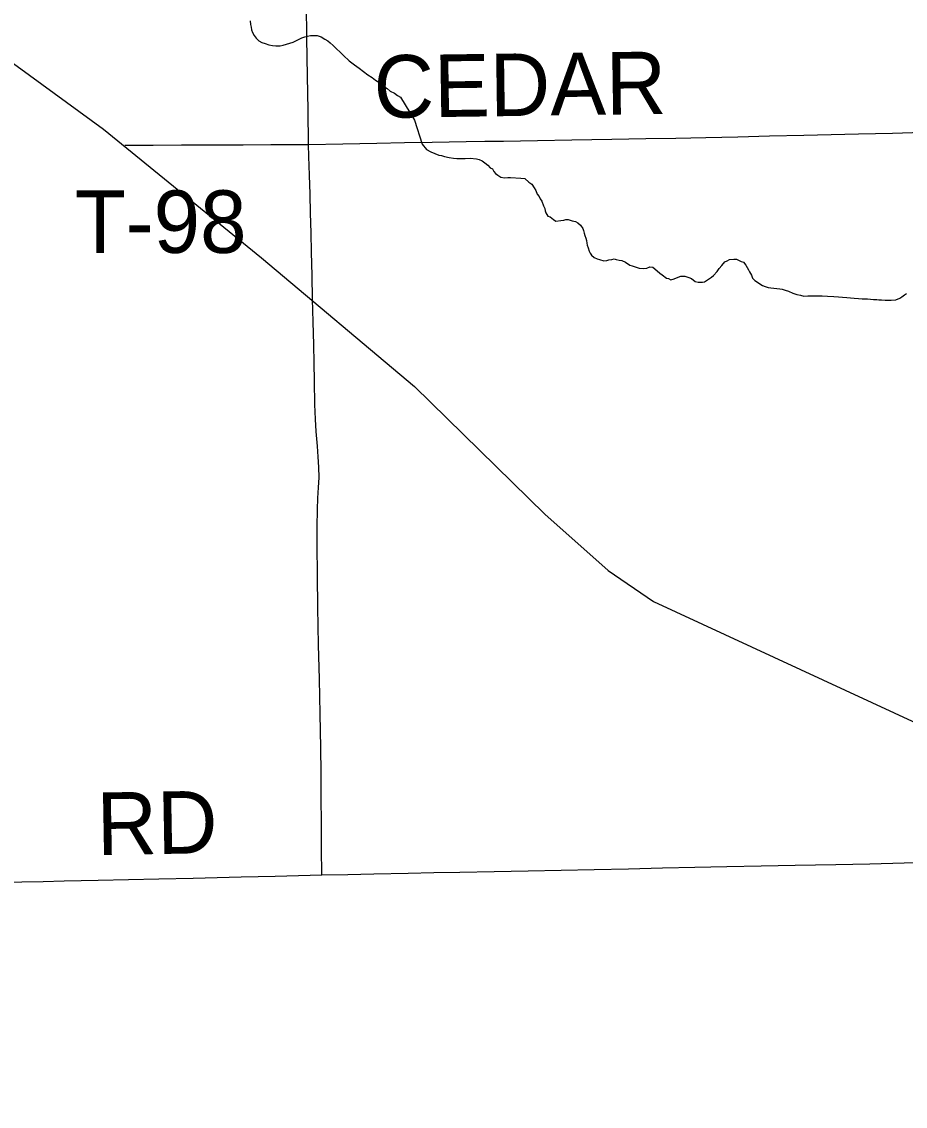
# Model space of a CAD drawing. Extents: x -11.4 to 84.1, y 11.1 to 59.
# Drawn here: x 31.559 to 32.362, y 45.761 to 46.747 of the extents above; entities that cross this region are included whole.
import ezdxf

# ---------------------------------------------------------------- set-up
doc = ezdxf.new("R2010")
doc.units = 0
for name, color, linetype in [('GM_X_County_Road', 7, 'Continuous'), ('GM_X_County_Road_Text', 7, 'Continuous'), ('GM_X_Minor_River', 7, 'Continuous'), ('GM_X_Rail_Line', 7, 'Continuous'), ('GM_X_Township_Road', 7, 'Continuous'), ('GM_X_Township_Road_Text', 7, 'Continuous')]:
    doc.layers.add(name, color=color, linetype=linetype)

msp = doc.modelspace()

# ---------------------------------------------------------------- linework, layer by layer
at = {"layer": 'GM_X_County_Road'}
msp.add_lwpolyline([(31.52787, 45.96386), (31.55893, 45.96467), (31.57804, 45.96516), (31.59715, 45.96566), (31.62821, 45.9663), (31.65581, 45.96686), (31.6834, 45.96744), (31.71446, 45.96819), (31.73633, 45.96872), (31.7582, 45.96924), (31.78925, 45.97002), (31.81035, 45.97055), (31.83145, 45.97107), (31.85514, 45.97151), (31.87883, 45.97196), (31.90989, 45.97264), (31.93349, 45.97316), (31.95709, 45.97367), (31.98815, 45.97428), (32.01921, 45.97489), (32.04922, 45.97548), (32.07924, 45.97607), (32.1103, 45.97674), (32.14137, 45.97742), (32.17056, 45.97805), (32.19975, 45.97869), (32.23081, 45.97932), (32.26187, 45.97994), (32.2803, 45.9803), (32.29872, 45.98067), (32.32978, 45.9813), (32.36085, 45.98193), (32.39191, 45.98256)], dxfattribs=at)
at = {"layer": 'GM_X_Minor_River'}
for points in [[(31.76638, 46.74748), (31.7668, 46.74406), (31.76721, 46.74178), (31.76762, 46.73912), (31.76841, 46.73685), (31.76996, 46.7342), (31.77189, 46.73156), (31.7742, 46.7293), (31.77687, 46.72781), (31.77993, 46.7267), (31.78336, 46.72559), (31.78679, 46.72487), (31.78984, 46.72452), (31.79364, 46.72456), (31.79629, 46.72534), (31.80538, 46.72809), (31.8084, 46.72964), (31.81105, 46.73081), (31.81332, 46.73197), (31.81597, 46.73276), (31.81862, 46.73355), (31.82128, 46.73395), (31.82432, 46.73399), (31.82736, 46.73401), (31.8308, 46.73291), (31.83424, 46.73066), (31.83692, 46.72917), (31.83922, 46.72729), (31.84191, 46.72504), (31.84499, 46.72202), (31.84806, 46.71901), (31.85114, 46.716), (31.85652, 46.71111), (31.86112, 46.70736), (31.86534, 46.70436), (31.86956, 46.70136), (31.87339, 46.69835), (31.87722, 46.69573), (31.88029, 46.69348), (31.88336, 46.69161), (31.88604, 46.68935), (31.88835, 46.68748), (31.89102, 46.68598), (31.89372, 46.68335), (31.89754, 46.68149), (31.90022, 46.67961), (31.9029, 46.67812), (31.91574, 46.65719)], [(31.91574, 46.65719), (31.92276, 46.63529), (31.92664, 46.63041), (31.93048, 46.62819), (31.9343, 46.62673), (31.93775, 46.62527), (31.94041, 46.62493), (31.94308, 46.62421), (31.94728, 46.62314), (31.95109, 46.62244), (31.95413, 46.62212), (31.96172, 46.62224), (31.96628, 46.62269), (31.97199, 46.62203), (31.97465, 46.62131), (31.97733, 46.62021), (31.97964, 46.61835), (31.98234, 46.61611), (31.98466, 46.61387), (31.98657, 46.61276), (31.98775, 46.6105), (31.9893, 46.60862), (31.99161, 46.60714), (31.9943, 46.60528), (31.99773, 46.60458), (32.00076, 46.60501), (32.00304, 46.60504), (32.01254, 46.60444), (32.01597, 46.60411), (32.01982, 46.60076), (32.02251, 46.5989), (32.02447, 46.59551), (32.02602, 46.59325), (32.02722, 46.58985), (32.02916, 46.5876), (32.02995, 46.58571), (32.0315, 46.58345), (32.03309, 46.5793), (32.03428, 46.57666), (32.03469, 46.57476), (32.0351, 46.57287), (32.03705, 46.56986), (32.03896, 46.56913), (32.04204, 46.5669), (32.04434, 46.56541), (32.04889, 46.56587), (32.05154, 46.56629), (32.05344, 46.5667), (32.05533, 46.56674), (32.05915, 46.56566), (32.0622, 46.56495), (32.06412, 46.56384), (32.06682, 46.5616), (32.06877, 46.55859), (32.06956, 46.5567), (32.06997, 46.55443), (32.07077, 46.55216), (32.07157, 46.54989), (32.07199, 46.54761), (32.07241, 46.54534), (32.07282, 46.54344), (32.07361, 46.54118), (32.07443, 46.53815), (32.0756, 46.53627), (32.07677, 46.53438), (32.07908, 46.53214), (32.08176, 46.53104), (32.08405, 46.53032), (32.08787, 46.52924), (32.09052, 46.52967), (32.09241, 46.53008), (32.09506, 46.5305), (32.09734, 46.53092), (32.09924, 46.53057), (32.10191, 46.52985), (32.1042, 46.52951), (32.10764, 46.52805), (32.11148, 46.52545), (32.11377, 46.52472), (32.11989, 46.52254), (32.12369, 46.52222), (32.1271, 46.52266), (32.12974, 46.52384), (32.1324, 46.52351), (32.13626, 46.52015), (32.13896, 46.51791), (32.14088, 46.51642), (32.14473, 46.51344), (32.14663, 46.51309), (32.14893, 46.51199), (32.15196, 46.5128), (32.15535, 46.51438), (32.15799, 46.51518), (32.16141, 46.51524), (32.16523, 46.51416), (32.16753, 46.51306), (32.17099, 46.51045), (32.17366, 46.50974)], [(32.17366, 46.50974), (32.17746, 46.5098), (32.17935, 46.51021), (32.18123, 46.51138), (32.18311, 46.51255), (32.18573, 46.51449), (32.18761, 46.51605), (32.19097, 46.51952), (32.19282, 46.52222), (32.19505, 46.52492), (32.19804, 46.52839), (32.19992, 46.52918), (32.20218, 46.53036), (32.20597, 46.5308), (32.20863, 46.53084), (32.21284, 46.52863), (32.21476, 46.5279), (32.21708, 46.52528), (32.21943, 46.52113), (32.22022, 46.51924), (32.22217, 46.51623), (32.22297, 46.51359), (32.22529, 46.51134), (32.2322, 46.50689), (32.2345, 46.50579), (32.23717, 46.50507), (32.23983, 46.50474), (32.2425, 46.5044), (32.24516, 46.50406), (32.24783, 46.50373), (32.25011, 46.50338), (32.25278, 46.50267), (32.25584, 46.50158), (32.25967, 46.49974), (32.26349, 46.49866), (32.26654, 46.49795), (32.26959, 46.49724), (32.27338, 46.4973), (32.2768, 46.49736), (32.28022, 46.49741), (32.28364, 46.49747), (32.28629, 46.49751), (32.29124, 46.49721), (32.29694, 46.49692), (32.30112, 46.49661), (32.30493, 46.4963), (32.30873, 46.49598), (32.31215, 46.49565), (32.31558, 46.49533), (32.31938, 46.49501), (32.32281, 46.49469), (32.32546, 46.49473), (32.32774, 46.49477), (32.33307, 46.4941), (32.33611, 46.49415), (32.33801, 46.4938), (32.34029, 46.49383), (32.34372, 46.49351), (32.34713, 46.49357), (32.34903, 46.4936), (32.35321, 46.49367), (32.35698, 46.49525), (32.35886, 46.49642), (32.36111, 46.49836), (32.36299, 46.49953)]]:
    msp.add_lwpolyline(points, dxfattribs=at)
at = {"layer": 'GM_X_Rail_Line'}
msp.add_lwpolyline([(31.09667, 47.00784), (31.1415, 46.99148), (31.18544, 46.9755), (31.63289, 46.64907), (31.77669, 46.5321), (31.91579, 46.41507), (32.03416, 46.29896), (32.09173, 46.24782), (32.13318, 46.21971), (32.55048, 46.02665), (32.76419, 45.92575), (32.90652, 45.86171), (32.9839, 45.81333), (33.01897, 45.78396), (33.0454, 45.76076)], dxfattribs=at)
at = {"layer": 'GM_X_Township_Road'}
for points in [[(31.81949, 46.63504), (31.81897, 46.6661), (31.81845, 46.69717), (31.81817, 46.71437), (31.81788, 46.73156), (31.81764, 46.76263)], [(31.79425, 46.63493), (31.80232, 46.63497), (31.81949, 46.63504), (31.85055, 46.63564), (31.88161, 46.63625), (31.90672, 46.63674), (31.93183, 46.63722), (31.96289, 46.63766), (31.97974, 46.63791), (31.99659, 46.63814), (32.02765, 46.63869), (32.05871, 46.63925), (32.07693, 46.63957), (32.09514, 46.6399), (32.1262, 46.64039), (32.15346, 46.64082), (32.18071, 46.64125), (32.20964, 46.64199), (32.23857, 46.64274), (32.26964, 46.64347), (32.29446, 46.64405), (32.31928, 46.64464), (32.35034, 46.64542), (32.37746, 46.64611)], [(31.65253, 46.63436), (31.67822, 46.63446), (31.70391, 46.63457), (31.73498, 46.63469), (31.76007, 46.6348), (31.78516, 46.6349), (31.79425, 46.63493)], [(31.83145, 45.97107), (31.83132, 45.99537), (31.83102, 46.06385), (31.83064, 46.08647), (31.82997, 46.11753), (31.82964, 46.13328), (31.8293, 46.14902), (31.82862, 46.18008), (31.82826, 46.1971), (31.82789, 46.21413), (31.82759, 46.24279), (31.82729, 46.27145), (31.82737, 46.2874), (31.82744, 46.30336), (31.82785, 46.31341), (31.82865, 46.32323), (31.82897, 46.3324), (31.82881, 46.34157), (31.82825, 46.35101), (31.82746, 46.36073), (31.82642, 46.37397), (31.8257, 46.38546), (31.82522, 46.39879), (31.82482, 46.42001), (31.8245, 46.43641), (31.82418, 46.45281), (31.82363, 46.47365), (31.82308, 46.49448), (31.82265, 46.51583), (31.82222, 46.53718), (31.8218, 46.55483), (31.82137, 46.5725), (31.82088, 46.58987), (31.82038, 46.60725), (31.81984, 46.62419), (31.81949, 46.63504)]]:
    msp.add_lwpolyline(points, dxfattribs=at)

# ---------------------------------------------------------------- texts
at = {"layer": 'GM_X_County_Road_Text'}
msp.add_text('RD', height=0.056818, rotation=0.98724, dxfattribs=at).set_placement((31.62731, 45.98908))
at = {"layer": 'GM_X_Township_Road_Text'}
for s, rotation, p in [('CEDAR', 0.81298, (31.87905, 46.65907)), ('T-98', 0.00001, (31.60686, 46.53644))]:
    msp.add_text(s, height=0.056818, rotation=rotation, dxfattribs=at).set_placement(p)

doc.saveas('drawing.dxf')
